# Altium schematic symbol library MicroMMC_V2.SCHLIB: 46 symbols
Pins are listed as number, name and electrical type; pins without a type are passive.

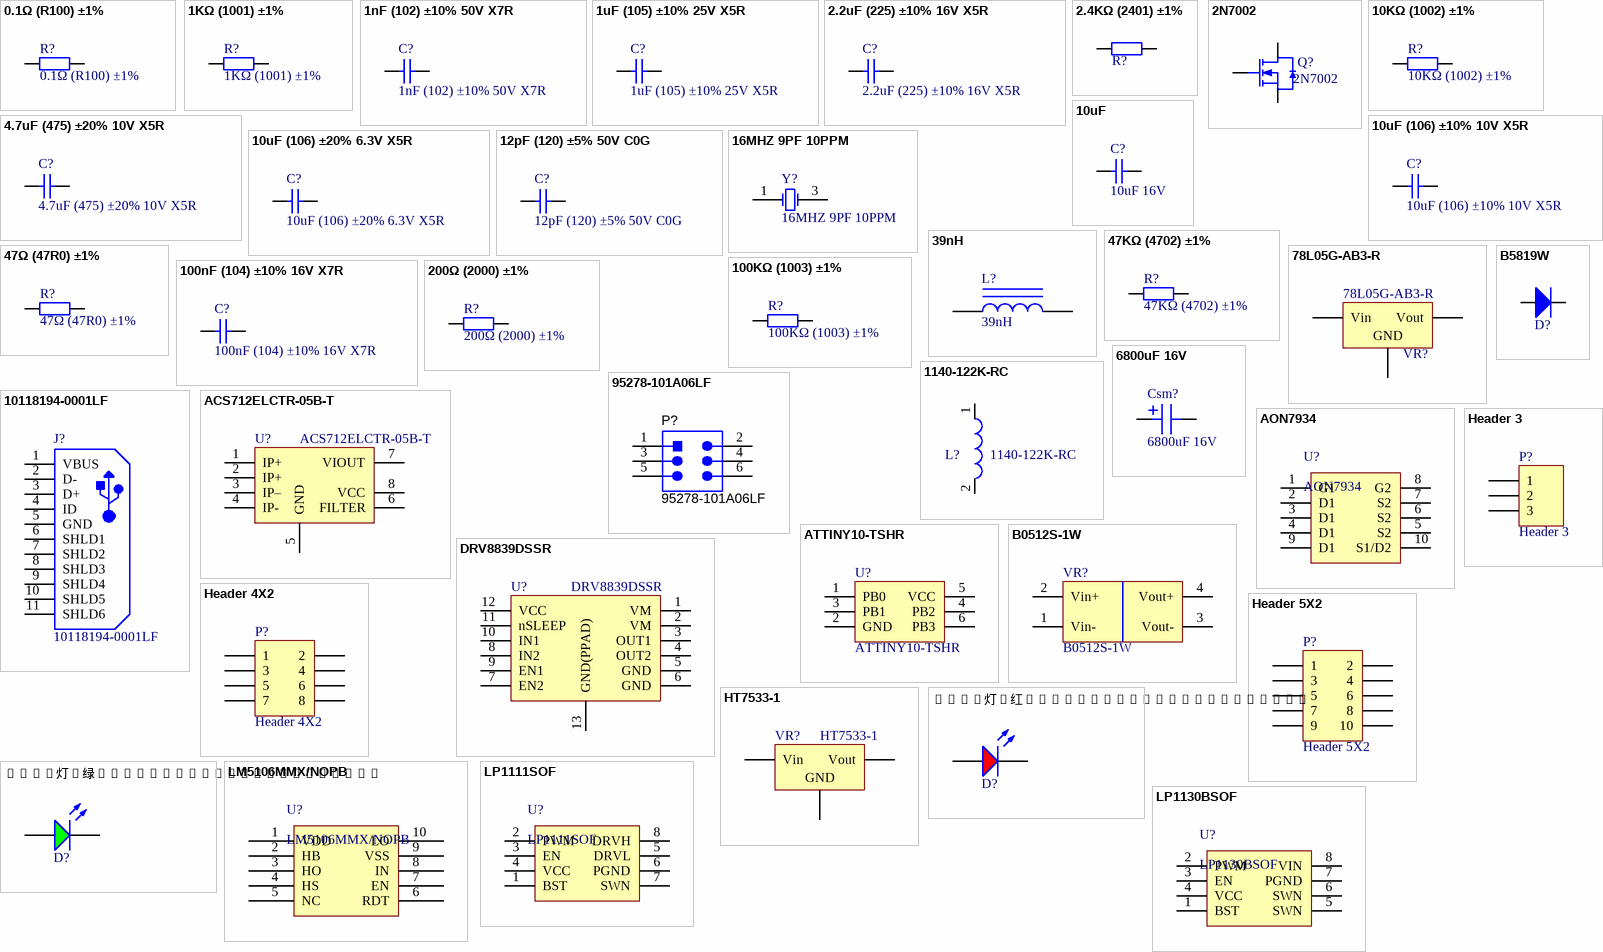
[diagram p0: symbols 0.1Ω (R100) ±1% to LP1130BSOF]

## 0.1Ω (R100) ±1%
designator R?
C25334 贴片电阻 1206
footprint 1206_R
pins: 1, 2

## 1KΩ (1001) ±1%
designator R?
C11702 贴片电阻 0402
footprint 0402_R
pins: 1, 2

## 1nF (102) ±10% 50V X7R
designator C?
C1523 贴片电容 0402
footprint 0402_C
pins: 1, 2

## 1uF (105) ±10% 25V X5R
designator C?
C52923 贴片电容 0402
footprint 0402_C
pins: 1, 2

## 2.2uF (225) ±10% 16V X5R
designator C?
C23630 贴片电容 0603
footprint 0603_C
pins: 1, 2

## 2.4KΩ (2401) ±1%
designator R?  (value not drawn)
C25882 贴片电阻 0402
footprint 0402_R
pins: 1, 2

## 2N7002
designator Q?
C8545 SOT-23-3
footprint SOT-23(SOT-23-3)
footprint SOT-23(SOT-23-3)
pins: 1 G, 2 S, 3 D

## 4.7uF (475) ±20% 10V X5R
designator C?
C23733 贴片电容 0402
footprint 0402_C
pins: 1, 2

## 10KΩ (1002) ±1%
designator R?
C25744 贴片电阻 0402
footprint 0402_R
pins: 1, 2

## 10uF
designator C?, comment 10uF 16V
C92487 10uF 16V 0603
footprint 0603_C
footprint 0603_C
pins: 1, 2

## 10uF (106) ±10% 10V X5R
designator C?
C19702 贴片电容 0603
footprint 0603_C
footprint 0603_C
pins: 1, 2

## 10uF (106) ±20% 6.3V X5R
designator C?
C15525 6.3V 0402
footprint 0402_C
pins: 1, 2

## 12pF (120) ±5% 50V C0G
designator C?
C1547 贴片电容 0402
footprint 0402_C
pins: 1, 2

## 16MHZ 9PF 10PPM
designator Y?
C13738 贴片晶振
footprint SMD-3225_4P
pins: 1 OSC1, 3 OSC2

## 39nH
designator L?
C26443 贴片电感 0402
footprint 0402_L
pins: 1, 2

## 47KΩ (4702) ±1%
designator R?
C25792 贴片电阻 0402
footprint 0402_R
pins: 1, 2

## 47Ω (47R0) ±1%
designator R?
C25118 贴片电阻 0402
footprint 0402_R
pins: 1, 2

## 78L05G-AB3-R
designator VR?
C71136 低压差线性稳压(LDO) SOT-89  12-5
footprint SOT-89(SOT-89-3)
pins: 1 Vout, 2 GND, 3 Vin

## 100KΩ (1003) ±1%
designator R?
C25741 贴片电阻 0402
footprint 0402_R
pins: 1, 2

## 100nF (104) ±10% 16V X7R
designator C?
C1525 贴片电容 0402
footprint 0402_C
pins: 1, 2

## 200Ω (2000) ±1%
designator R?
C25087 贴片电阻 0402
footprint 0402_R
footprint 0402_R
pins: 1, 2

## 1140-122K-RC
designator L?
C1329703 Radial; MF: Bourns
footprint INDRD2921W163D3810H2616P
footprint INDRD2921W163D3810H2616P
pins: 1, 2

## 6800uF 16V
designator Csm?
C47893 引线型铝电解电容 Radial,16x25mm; Manufacturer 1: KEMET; Manufacturer Part Number 1: ESK688M010AM2AA
footprint 6800uF 16V 16*25 (LCSC C47893)
pins: 1, 2

## 95278-101A06LF
designator P?
C178294; Manufacturer: Amphenol FCI; Power Rating: 100 mW; Tolerance: 1%; Resistance: 49.9 Ohm; Case\Package: 0603; Voltage Rating: 50 V
footprint AMPM-95278-101A06LF_V (SMD, 6-Leads, Body 7.26x4.83mm, Pitch 2.54mm)
pins: 1, 2, 3, 4, 5, 6

## 10118194-0001LF
designator J?
C132563; Manufacturer: Amphenol FCI; Body Orientation: RightAngle; Number of Contacts: 5; Pitch: 0.65mm; Gender: RCP; Rad Hard: No
footprint FCI-10118194-0001LF-5_V (SMD, 5-Leads, Body 7x5mm, Pitch 0.65 mm)
pins: 1 VBUS, 2 D-, 3 D+, 4 ID, 5 GND, 6 SHLD1, 7 SHLD2, 8 SHLD3, 9 SHLD4, 10 SHLD5, 11 SHLD6

## ACS712ELCTR-05B-T
designator U?
C44471 电流传感器 SOIC-8_3.9X4.9X1.27P
footprint SOIC-8_150mil
footprint ACS712ELCTR-20A-T
pins: 1 IP+, 2 IP+, 3 IP–, 4 IP-, 5 GND, 6 FILTER, 7 VIOUT, 8 VCC

## AON7934
designator U?
C485677 DFN-8_2EP_3.0X3.0X0.65P
pins: 1 G1, 2 D1, 3 D1, 4 D1, 5 S2, 6 S2, 7 S2, 8 G2, 9 D1, 10 S1/D2

## ATTINY10-TSHR
designator U?
C128438 SOT-23-6L Extended
footprint 6ST1_ATM (ATTINY10)
pins: 1 PB0 "(PCINT0/TPIDATA /OC0A/ADC0/AIN0)", 2 GND, 3 PB1 "(PCINT1/TPICLK/CLKI/ICP0/OC0B/ADC1/AIN1)", 4 PB2 "(T0/CLKO/PCINT2/INT0/ADC2)", 5 VCC, 6 PB3 "(RESET/PCINT3/ADC3)"

## B0512S-1W
designator VR?
Isolated DCDC 0512 C133158
footprint B0512S-1W
pins: 1 Vin-, 2 Vin+, 3 Vout-, 4 Vout+

## B5819W
designator D?  (value not drawn)
C8598 SOD-123
footprint SOD-123
pins: 1 A, 2 K

## DRV8839DSSR
designator U?
C128627 WSON-12_EP_2.0X3.0X0.5P Extended
footprint DSS12_P9X2
pins: 1 VM, 2 VM, 3 OUT1, 4 OUT2, 5 GND, 6 GND, 7 EN2, 8 IN2, 9 EN1, 10 IN1, 11 nSLEEP, 12 VCC, 13 GND(PPAD)

## Header 3
designator P?
C124376
signal-integrity model Connector
footprint HDR2.54-LI-3P (排针，3脚)
pins: 1, 2, 3

## Header 4X2
designator P?
C124386
signal-integrity model Connector
footprint HDR2.54-LI-2x4P (双排排针，4x2脚)
pins: 1, 2, 3, 4, 5, 6, 7, 8

## Header 5X2
designator P?
C124387
footprint HDR2X5 (Connector; Header; 5x2 Position)
signal-integrity model Connector
footprint HDR2.54-LI-2x5P (双排排针，5x2脚)
pins: 1, 2, 3, 4, 5, 6, 7, 8, 9, 10

## HT7533-1
designator VR?
C14289 低压差线性稳压(LDO) SOT-89 5-3.3
footprint SOT-89(SOT-89-3)
footprint SOT-89(SOT-89-3)
pins: 1 GND, 2 Vin, 3 Vout

## LED_灯_红_Iv=100-120_λd=615-630
designator D?  (value not drawn)
C2286 发光二极管 LED_0603
footprint 0603_LED_S1
pins: A, K

## LED_灯_绿_Iv=112-285_λd=520-535
designator D?  (value not drawn)
C72043 发光二极管 LED_0603
footprint 0603_LED_S1
pins: A, K

## LM5106MMX/NOPB
designator U?
C91879 VSSOP-10_3.0X3.0X0.5P
pins: 1 VDD, 2 HB, 3 HO, 4 HS, 5 NC, 6 RDT, 7 EN, 8 IN, 9 VSS, 10 LO

## LP1111SOF
designator U?
C387724 SOP-8_EP_3.9X4.9X1.27P
pins: 1 BST, 2 PWM, 3 EN, 4 VCC, 5 DRVL, 6 PGND, 7 SWN, 8 DRVH

## LP1130BSOF
designator U?
C387697 SOP-8_EP_3.9X4.9X1.27P
footprint SOP_8_LP1130B
pins: 1 BST, 2 PWM, 3 EN, 4 VCC, 5 SWN, 6 SWN, 7 PGND, 8 VIN

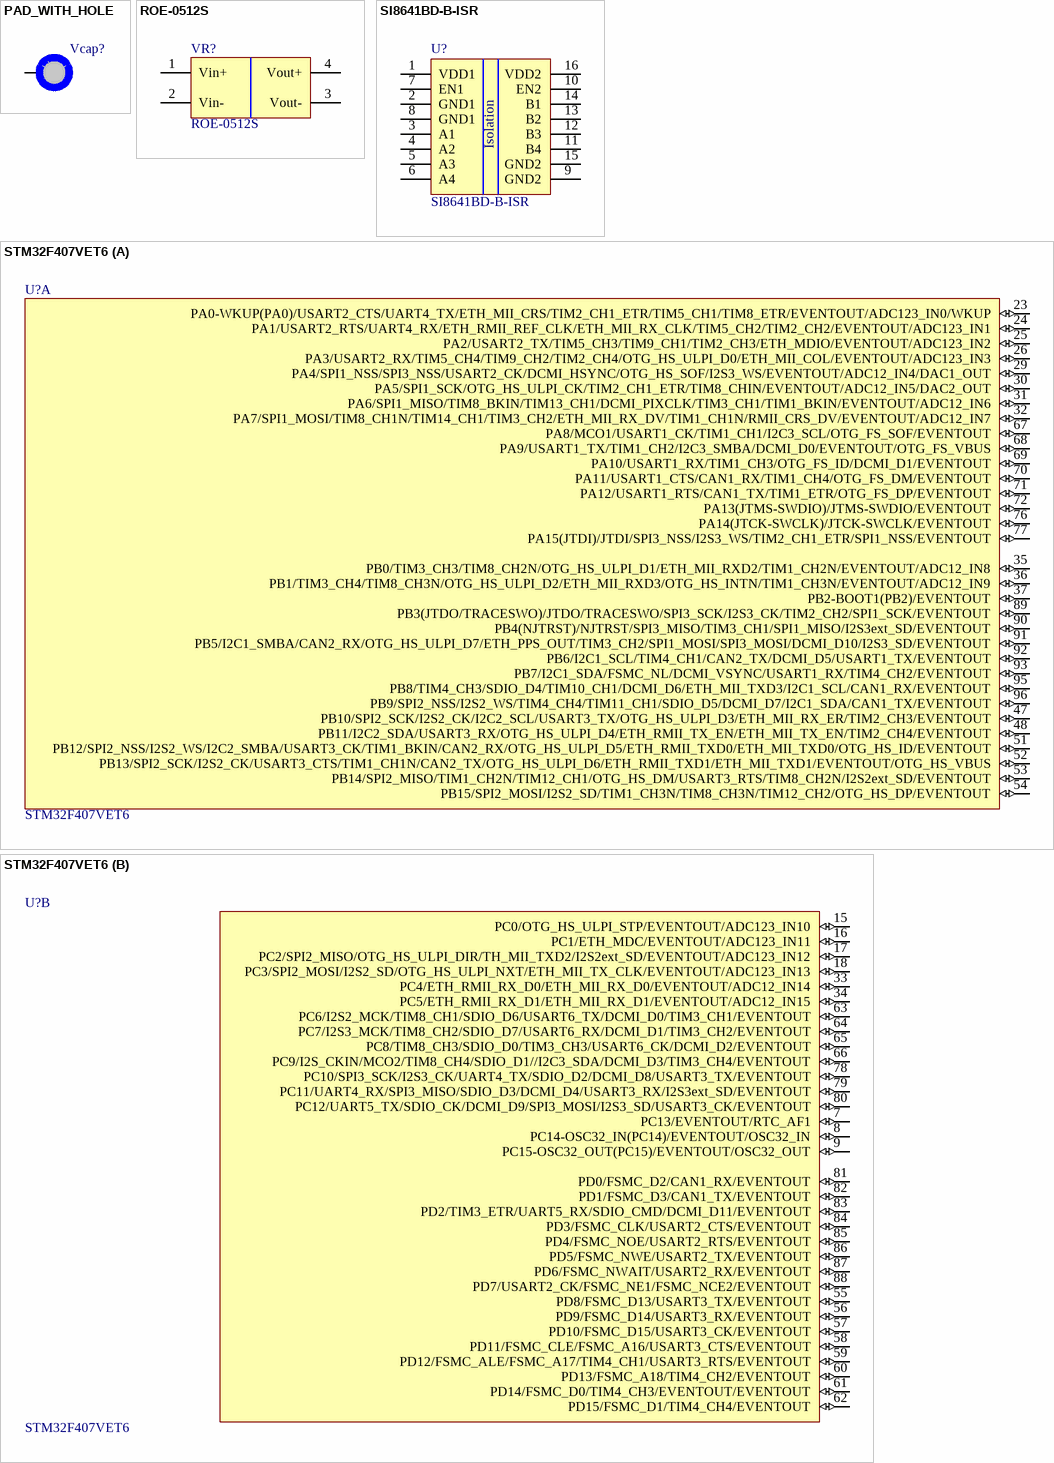
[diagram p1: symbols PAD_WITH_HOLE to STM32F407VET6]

## PAD_WITH_HOLE
designator Vcap?  (value not drawn)
pins: 1

## ROE-0512S
designator VR?
Isolated DC/DC Converters 1W 5Vin 12Vout 84mA SIP4
footprint ROE1205S
pins: 1 Vin+, 2 Vin-, 3 Vout-, 4 Vout+

## SI8641BD-B-ISR
designator U?
C461891 SOIC-16_7.5X10.3X1.27P Extended
footprint SOIC-16W_SIL (SI8641BD-B-ISR)
pins: 1 VDD1, 2 GND1, 3 A1, 4 A2, 5 A3, 6 A4, 7 EN1, 8 GND1, 9 GND2, 10 EN2, 11 B4, 12 B3, 13 B2, 14 B1, 15 GND2, 16 VDD2

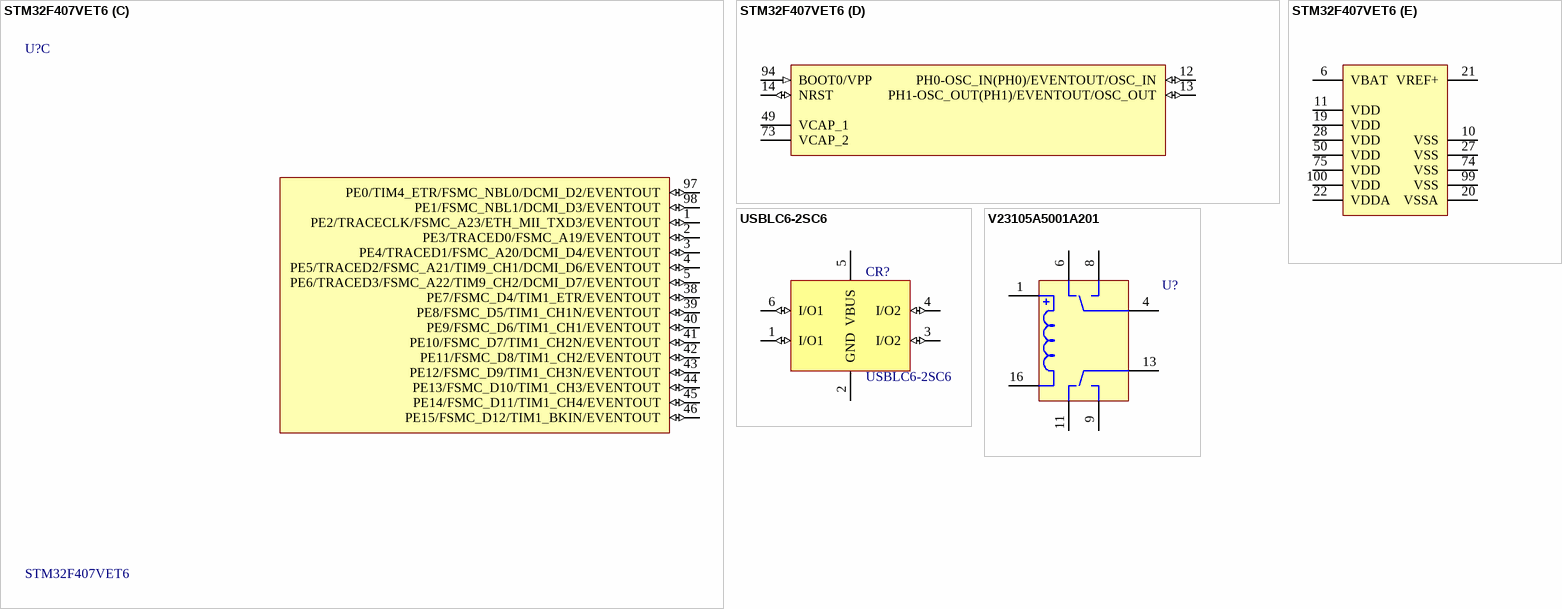
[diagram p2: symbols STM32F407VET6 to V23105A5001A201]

## STM32F407VET6
designator U?
C28730 ARM
footprint LQFP-100_14x14x05P
part A pins: 23 PA0-WKUP(PA0)/USART2_CTS/UART4_TX/ETH_MII_CRS/TIM2_CH1_ETR/TIM5_CH1/TIM8_ETR/EVENTOUT/ADC123_IN0/WKUP (io), 24 PA1/USART2_RTS/UART4_RX/ETH_RMII_REF_CLK/ETH_MII_RX_CLK/TIM5_CH2/TIM2_CH2/EVENTOUT/ADC123_IN1 (io), 25 PA2/USART2_TX/TIM5_CH3/TIM9_CH1/TIM2_CH3/ETH_MDIO/EVENTOUT/ADC123_IN2 (io), 26 PA3/USART2_RX/TIM5_CH4/TIM9_CH2/TIM2_CH4/OTG_HS_ULPI_D0/ETH_MII_COL/EVENTOUT/ADC123_IN3 (io), 29 PA4/SPI1_NSS/SPI3_NSS/USART2_CK/DCMI_HSYNC/OTG_HS_SOF/I2S3_WS/EVENTOUT/ADC12_IN4/DAC1_OUT (io), 30 PA5/SPI1_SCK/OTG_HS_ULPI_CK/TIM2_CH1_ETR/TIM8_CHIN/EVENTOUT/ADC12_IN5/DAC2_OUT (io), 31 PA6/SPI1_MISO/TIM8_BKIN/TIM13_CH1/DCMI_PIXCLK/TIM3_CH1/TIM1_BKIN/EVENTOUT/ADC12_IN6 (io), 32 PA7/SPI1_MOSI/TIM8_CH1N/TIM14_CH1/TIM3_CH2/ETH_MII_RX_DV/TIM1_CH1N/RMII_CRS_DV/EVENTOUT/ADC12_IN7 (io), 35 PB0/TIM3_CH3/TIM8_CH2N/OTG_HS_ULPI_D1/ETH_MII_RXD2/TIM1_CH2N/EVENTOUT/ADC12_IN8 (io), 36 PB1/TIM3_CH4/TIM8_CH3N/OTG_HS_ULPI_D2/ETH_MII_RXD3/OTG_HS_INTN/TIM1_CH3N/EVENTOUT/ADC12_IN9 (io), 37 PB2-BOOT1(PB2)/EVENTOUT (io), 47 PB10/SPI2_SCK/I2S2_CK/I2C2_SCL/USART3_TX/OTG_HS_ULPI_D3/ETH_MII_RX_ER/TIM2_CH3/EVENTOUT (io), 48 PB11/I2C2_SDA/USART3_RX/OTG_HS_ULPI_D4/ETH_RMII_TX_EN/ETH_MII_TX_EN/TIM2_CH4/EVENTOUT (io), 51 PB12/SPI2_NSS/I2S2_WS/I2C2_SMBA/USART3_CK/TIM1_BKIN/CAN2_RX/OTG_HS_ULPI_D5/ETH_RMII_TXD0/ETH_MII_TXD0/OTG_HS_ID/EVENTOUT (io), 52 PB13/SPI2_SCK/I2S2_CK/USART3_CTS/TIM1_CH1N/CAN2_TX/OTG_HS_ULPI_D6/ETH_RMII_TXD1/ETH_MII_TXD1/EVENTOUT/OTG_HS_VBUS (io), 53 PB14/SPI2_MISO/TIM1_CH2N/TIM12_CH1/OTG_HS_DM/USART3_RTS/TIM8_CH2N/I2S2ext_SD/EVENTOUT (io), 54 PB15/SPI2_MOSI/I2S2_SD/TIM1_CH3N/TIM8_CH3N/TIM12_CH2/OTG_HS_DP/EVENTOUT (io), 67 PA8/MCO1/USART1_CK/TIM1_CH1/I2C3_SCL/OTG_FS_SOF/EVENTOUT (io), 68 PA9/USART1_TX/TIM1_CH2/I2C3_SMBA/DCMI_D0/EVENTOUT/OTG_FS_VBUS (io), 69 PA10/USART1_RX/TIM1_CH3/OTG_FS_ID/DCMI_D1/EVENTOUT (io), 70 PA11/USART1_CTS/CAN1_RX/TIM1_CH4/OTG_FS_DM/EVENTOUT (io), 71 PA12/USART1_RTS/CAN1_TX/TIM1_ETR/OTG_FS_DP/EVENTOUT (io), 72 PA13(JTMS-SWDIO)/JTMS-SWDIO/EVENTOUT (io), 76 PA14(JTCK-SWCLK)/JTCK-SWCLK/EVENTOUT (io), 77 PA15(JTDI)/JTDI/SPI3_NSS/I2S3_WS/TIM2_CH1_ETR/SPI1_NSS/EVENTOUT (io), 89 PB3(JTDO/TRACESWO)/JTDO/TRACESWO/SPI3_SCK/I2S3_CK/TIM2_CH2/SPI1_SCK/EVENTOUT (io), 90 PB4(NJTRST)/NJTRST/SPI3_MISO/TIM3_CH1/SPI1_MISO/I2S3ext_SD/EVENTOUT (io), 91 PB5/I2C1_SMBA/CAN2_RX/OTG_HS_ULPI_D7/ETH_PPS_OUT/TIM3_CH2/SPI1_MOSI/SPI3_MOSI/DCMI_D10/I2S3_SD/EVENTOUT (io), 92 PB6/I2C1_SCL/TIM4_CH1/CAN2_TX/DCMI_D5/USART1_TX/EVENTOUT (io), 93 PB7/I2C1_SDA/FSMC_NL/DCMI_VSYNC/USART1_RX/TIM4_CH2/EVENTOUT (io), 95 PB8/TIM4_CH3/SDIO_D4/TIM10_CH1/DCMI_D6/ETH_MII_TXD3/I2C1_SCL/CAN1_RX/EVENTOUT (io), 96 PB9/SPI2_NSS/I2S2_WS/TIM4_CH4/TIM11_CH1/SDIO_D5/DCMI_D7/I2C1_SDA/CAN1_TX/EVENTOUT (io)
part B pins: 7 PC13/EVENTOUT/RTC_AF1 (io), 8 PC14-OSC32_IN(PC14)/EVENTOUT/OSC32_IN (io), 9 PC15-OSC32_OUT(PC15)/EVENTOUT/OSC32_OUT (io), 15 PC0/OTG_HS_ULPI_STP/EVENTOUT/ADC123_IN10 (io), 16 PC1/ETH_MDC/EVENTOUT/ADC123_IN11 (io), 17 PC2/SPI2_MISO/OTG_HS_ULPI_DIR/TH_MII_TXD2/I2S2ext_SD/EVENTOUT/ADC123_IN12 (io), 18 PC3/SPI2_MOSI/I2S2_SD/OTG_HS_ULPI_NXT/ETH_MII_TX_CLK/EVENTOUT/ADC123_IN13 (io), 33 PC4/ETH_RMII_RX_D0/ETH_MII_RX_D0/EVENTOUT/ADC12_IN14 (io), 34 PC5/ETH_RMII_RX_D1/ETH_MII_RX_D1/EVENTOUT/ADC12_IN15 (io), 55 PD8/FSMC_D13/USART3_TX/EVENTOUT (io), 56 PD9/FSMC_D14/USART3_RX/EVENTOUT (io), 57 PD10/FSMC_D15/USART3_CK/EVENTOUT (io), 58 PD11/FSMC_CLE/FSMC_A16/USART3_CTS/EVENTOUT (io), 59 PD12/FSMC_ALE/FSMC_A17/TIM4_CH1/USART3_RTS/EVENTOUT (io), 60 PD13/FSMC_A18/TIM4_CH2/EVENTOUT (io), 61 PD14/FSMC_D0/TIM4_CH3/EVENTOUT/EVENTOUT (io), 62 PD15/FSMC_D1/TIM4_CH4/EVENTOUT (io), 63 PC6/I2S2_MCK/TIM8_CH1/SDIO_D6/USART6_TX/DCMI_D0/TIM3_CH1/EVENTOUT (io), 64 PC7/I2S3_MCK/TIM8_CH2/SDIO_D7/USART6_RX/DCMI_D1/TIM3_CH2/EVENTOUT (io), 65 PC8/TIM8_CH3/SDIO_D0/TIM3_CH3/USART6_CK/DCMI_D2/EVENTOUT (io), 66 PC9/I2S_CKIN/MCO2/TIM8_CH4/SDIO_D1//I2C3_SDA/DCMI_D3/TIM3_CH4/EVENTOUT (io), 78 PC10/SPI3_SCK/I2S3_CK/UART4_TX/SDIO_D2/DCMI_D8/USART3_TX/EVENTOUT (io), 79 PC11/UART4_RX/SPI3_MISO/SDIO_D3/DCMI_D4/USART3_RX/I2S3ext_SD/EVENTOUT (io), 80 PC12/UART5_TX/SDIO_CK/DCMI_D9/SPI3_MOSI/I2S3_SD/USART3_CK/EVENTOUT (io), 81 PD0/FSMC_D2/CAN1_RX/EVENTOUT (io), 82 PD1/FSMC_D3/CAN1_TX/EVENTOUT (io), 83 PD2/TIM3_ETR/UART5_RX/SDIO_CMD/DCMI_D11/EVENTOUT (io), 84 PD3/FSMC_CLK/USART2_CTS/EVENTOUT (io), 85 PD4/FSMC_NOE/USART2_RTS/EVENTOUT (io), 86 PD5/FSMC_NWE/USART2_TX/EVENTOUT (io), 87 PD6/FSMC_NWAIT/USART2_RX/EVENTOUT (io), 88 PD7/USART2_CK/FSMC_NE1/FSMC_NCE2/EVENTOUT (io)
part C pins: 1 PE2/TRACECLK/FSMC_A23/ETH_MII_TXD3/EVENTOUT (io), 2 PE3/TRACED0/FSMC_A19/EVENTOUT (io), 3 PE4/TRACED1/FSMC_A20/DCMI_D4/EVENTOUT (io), 4 PE5/TRACED2/FSMC_A21/TIM9_CH1/DCMI_D6/EVENTOUT (io), 5 PE6/TRACED3/FSMC_A22/TIM9_CH2/DCMI_D7/EVENTOUT (io), 38 PE7/FSMC_D4/TIM1_ETR/EVENTOUT (io), 39 PE8/FSMC_D5/TIM1_CH1N/EVENTOUT (io), 40 PE9/FSMC_D6/TIM1_CH1/EVENTOUT (io), 41 PE10/FSMC_D7/TIM1_CH2N/EVENTOUT (io), 42 PE11/FSMC_D8/TIM1_CH2/EVENTOUT (io), 43 PE12/FSMC_D9/TIM1_CH3N/EVENTOUT (io), 44 PE13/FSMC_D10/TIM1_CH3/EVENTOUT (io), 45 PE14/FSMC_D11/TIM1_CH4/EVENTOUT (io), 46 PE15/FSMC_D12/TIM1_BKIN/EVENTOUT (io), 97 PE0/TIM4_ETR/FSMC_NBL0/DCMI_D2/EVENTOUT (io), 98 PE1/FSMC_NBL1/DCMI_D3/EVENTOUT (io)
part D pins: 12 PH0-OSC_IN(PH0)/EVENTOUT/OSC_IN (io), 13 PH1-OSC_OUT(PH1)/EVENTOUT/OSC_OUT (io), 14 NRST (io), 49 VCAP_1 (power), 73 VCAP_2 (power), 94 BOOT0/VPP (in)
part E pins: 6 VBAT, 10 VSS, 11 VDD, 19 VDD, 20 VSSA, 21 VREF+, 22 VDDA, 27 VSS, 28 VDD, 50 VDD, 74 VSS, 75 VDD, 99 VSS, 100 VDD

## USBLC6-2SC6
designator CR?
C7519 SOT-23-6L; Built_By: EMA_UL_Team; Vendor: STMicroelectronics; SourceLibrary: Update_database_2020-10-15; Type: DEV
footprint SOT23-6L_STM (USBLC62SC6)
pins: 1 I/O1 (io), 2 GND, 3 I/O2 (io), 4 I/O2 (io), 5 VBUS, 6 I/O1 (io)

## V23105A5001A201
designator U?  (value not drawn)
3A 5V; Manufacturer: TE Connectivity Axicom; Throw Configuration: DPDT; Coil Resistance: 167R; Coil Current: 29.76mA; Max Voltage Rating (AC): 250V; Max Voltage Rating (DC): 220V; Coil Type: Non-Latching; Coil Power: 150mW; Relay Type: Relay; Actuating System: AC/DC; Insertion Loss: -0.27dB; Ratings: IP67; Approvals: cULus
footprint Relay_V23105A5001A201 (V23105A5001A201)
pins: 1, 4, 6 1, 8, 9, 11, 13, 16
